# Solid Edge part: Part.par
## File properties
Author: TIET
Template: iso metric part.par
Last saved by: SOFT
Revision: 5
Application: Solid Edge
Accuracy: 0.990
Username: TIET
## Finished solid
Body 1: solid body, 34 faces, 81 edges, 46 vertices.
  Faces by surface: plane 28, cylinder 6
  Edges by curve: line 67, circle 14
Bounding box of the edges (mm): 92.000 x 170.000 x 106.000, from (-46, -30, -30) to (46, 140, 76).
Cylindrical faces by radius (mm): R8 x2, R16 x2, R18 x1, R30 x1
Planar faces by outward normal: +x 5, +y 3, +z 4, -x 5, -y 5, -z 4, oblique 2
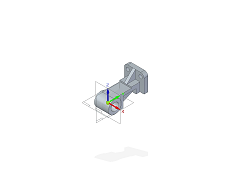
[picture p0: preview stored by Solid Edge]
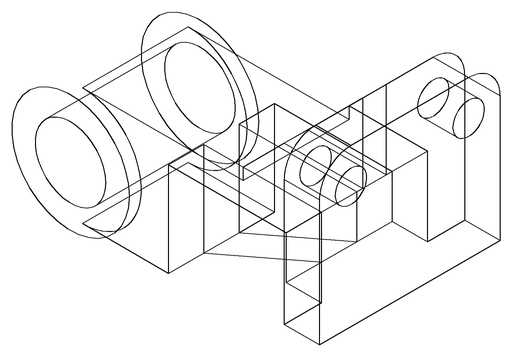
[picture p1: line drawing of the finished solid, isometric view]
